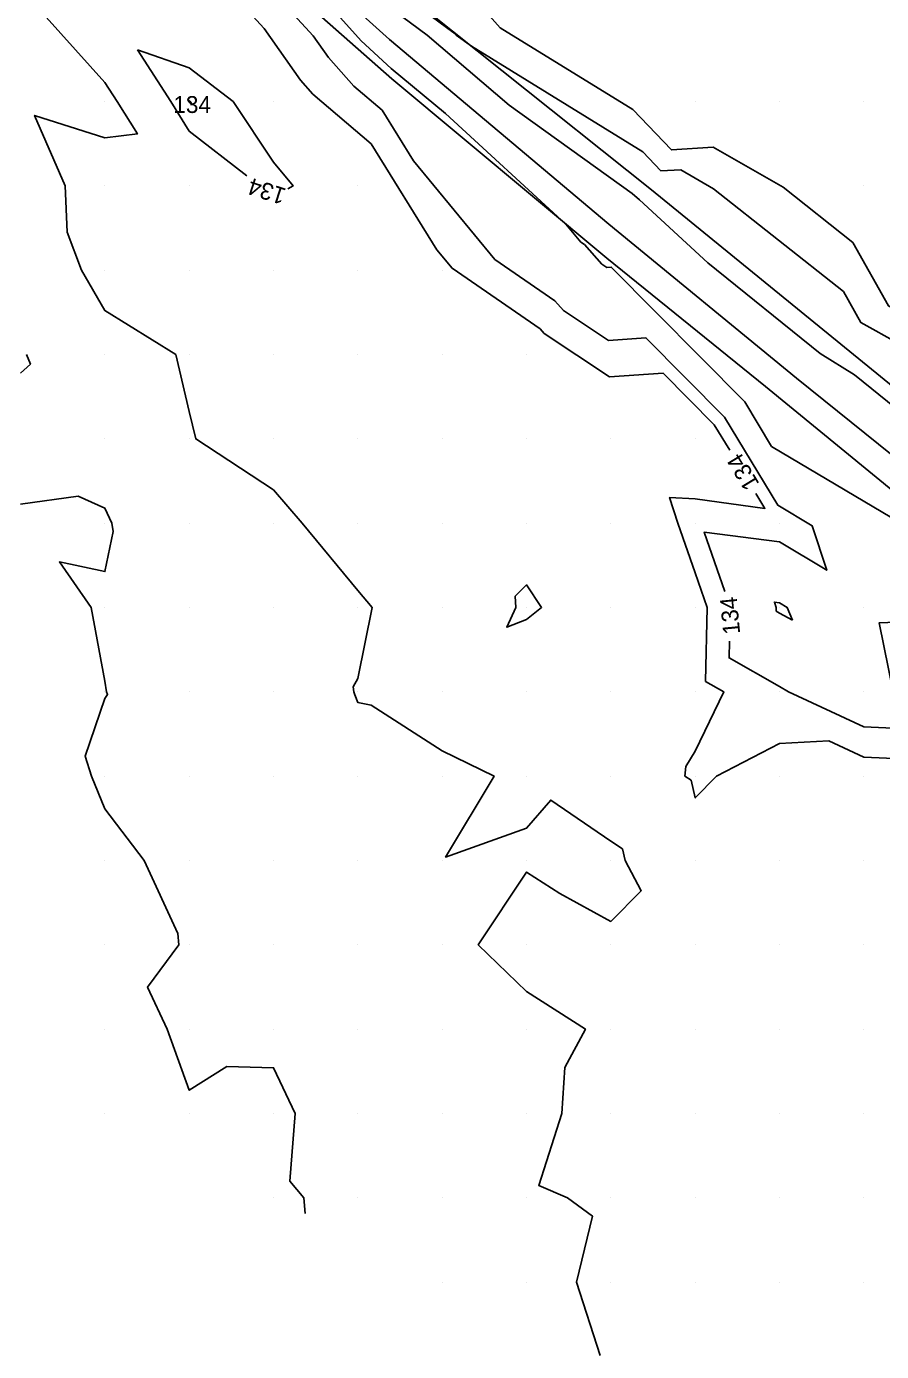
# Model space of a CAD drawing. Extents: x 2354170 to 2357230, y 866100 to 868290.
# Drawn here: x 2354990.7 to 2355092.1, y 867231.8 to 867388.9 of the extents above; entities that cross this region are included whole.
import ezdxf

# ---------------------------------------------------------------- set-up
doc = ezdxf.new("R2010")
doc.units = 0
for name, color, linetype in [('Default', 7, 'Continuous'), ('DTM Contours Minor', 7, 'Continuous'), ('DTM Contours Minor Text', 7, 'Continuous'), ('Exist DTM QL2 LIDAR Elevation Point', 7, 'Continuous'), ('PH Exist DTM Breakline', 7, 'Continuous')]:
    doc.layers.add(name, color=color, linetype=linetype)

msp = doc.modelspace()

# ---------------------------------------------------------------- linework, layer by layer
at = {"layer": 'Default'}
for points in [[(2355106.88, 867346.9), (2355102.18, 867350.64), (2355092.9, 867355.77), (2355088.66, 867363.29), (2355080.4, 867369.84), (2355072.11, 867374.59), (2355067.14, 867374.28), (2355062.56, 867379.07), (2355046.85, 867388.77), (2355044.03, 867391.9), (2355032.74, 867398.24), (2355030.89, 867399.72), (2355029.35, 867400.43), (2355028.09, 867400.68), (2355026.45, 867401.96)], [(2355002.92, 867397.36), (2355007.73, 867400.8), (2355018.86, 867388.68), (2355023.14, 867382.55), (2355024.61, 867380.9), (2355031.55, 867374.98), (2355039.34, 867362.43), (2355041.14, 867360.25), (2355051.56, 867353.04), (2355052.04, 867352.51), (2355059.8, 867347.37), (2355066.16, 867347.79), (2355072.22, 867341.68), (2355074.06, 867338.65)], [(2355198.39, 867249.97), (2355187.27, 867259.93), (2355180.42, 867265.38), (2355175.56, 867269.74), (2355167.49, 867277.11), (2355152.65, 867292.54), (2355145.83, 867297.52), (2355143.62, 867300.08), (2355127.24, 867315.15), (2355122.38, 867319.86), (2355121.91, 867320.21), (2355110.98, 867330.24), (2355105.72, 867333.97), (2355088.86, 867347.6), (2355084.78, 867350.15), (2355071.45, 867360.89), (2355063.34, 867368.37), (2355062.48, 867369.12), (2355047.91, 867379.58), (2355038.19, 867387.88), (2355031.33, 867392.97)], [(2354993.01, 867390.02), (2354999.97, 867382.26), (2355001.42, 867380.02), (2355003.81, 867376.18), (2354999.97, 867375.69), (2354991.63, 867378.36), (2354995.27, 867370.01), (2354995.47, 867364.52), (2354997.2, 867360.01), (2354999.97, 867355.22), (2355008.38, 867350.01), (2355009.97, 867343.27), (2355010.73, 867340.01), (2355019.97, 867333.95), (2355023.36, 867330.01), (2355029.97, 867322.03), (2355031.65, 867320.01), (2355029.97, 867311.6), (2355029.4, 867310.59), (2355029.48, 867310.01), (2355029.6, 867309.64), (2355029.97, 867308.73), (2355031.55, 867308.43), (2355039.97, 867303.01), (2355046.12, 867300.01), (2355040.36, 867290.41), (2355049.97, 867293.84), (2355052.83, 867297.16), (2355059.97, 867292.31), (2355061.34, 867291.38), (2355061.66, 867290.01), (2355063.56, 867286.42), (2355059.97, 867282.77), (2355053.92, 867286.07), (2355049.97, 867288.63), (2355044.23, 867280.01), (2355049.97, 867274.48), (2355056.95, 867270.01), (2355054.52, 867265.47), (2355054.14, 867260.01), (2355051.41, 867251.45), (2355054.82, 867250.01), (2355057.78, 867247.82), (2355055.9, 867240.01), (2355058.69, 867231.3)], [(2355027.2, 867390.72), (2355030.35, 867387.23), (2355033.92, 867383.94), (2355040.35, 867378.59), (2355054.64, 867365.47), (2355056.4, 867363.35), (2355056.82, 867363.06), (2355058.9, 867360.74), (2355059.5, 867360.34), (2355060, 867360.38), (2355075.85, 867344.38), (2355079.03, 867339.12), (2355096.48, 867328.73)], [(2355003.84, 867386.15), (2355009.97, 867384.03), (2355015.16, 867380.02), (2355019.97, 867372.82), (2355022.27, 867370.01), (2355021.65, 867369.66)], [(2355016.79, 867371.22), (2355009.97, 867376.52), (2355007.8, 867380.02), (2355003.84, 867386.15)], [(2354990.66, 867350.01), (2354991.13, 867348.86), (2354989.97, 867347.79)], [(2354989.97, 867332.28), (2354996.79, 867333.2), (2354999.97, 867331.77), (2355000.77, 867330.01), (2355000.94, 867329.04), (2354999.97, 867324.26), (2354994.57, 867325.42), (2354998.33, 867320.01), (2354999.97, 867311.26), (2355000.15, 867310.01), (2355000.29, 867309.7), (2354999.97, 867309.22), (2354997.62, 867302.36), (2354998.37, 867300.01), (2354999.97, 867296.14), (2355004.62, 867290.01), (2355008.63, 867281.36), (2355008.74, 867280.01), (2355005.03, 867274.96), (2355007.34, 867270.01), (2355009.97, 867262.75), (2355014.44, 867265.55), (2355019.97, 867265.43), (2355022.53, 867260.01), (2355021.91, 867251.95), (2355023.54, 867250.01), (2355023.71, 867248.15)], [(2355077.17, 867333.52), (2355078.23, 867331.75), (2355069.97, 867332.88), (2355066.93, 867333.06), (2355067.92, 867330.01), (2355069.97, 867324.13), (2355071.39, 867320.01), (2355071.2, 867311.24), (2355073.35, 867310.01), (2355069.97, 867302.95), (2355068.86, 867301.13), (2355068.75, 867300.01), (2355069.48, 867299.52), (2355069.97, 867297.42), (2355072.49, 867300.01), (2355079.97, 867303.89), (2355085.8, 867304.19), (2355089.97, 867302.24), (2355098.06, 867301.92), (2355096.44, 867310.01), (2355095.55, 867314.44), (2355099.59, 867314.59)], [(2355048.7, 867320.01), (2355048.63, 867321.35), (2355049.97, 867322.68), (2355051.75, 867320.01), (2355049.97, 867318.57), (2355047.62, 867317.66), (2355048.7, 867320.01)], [(2355081.49, 867318.49), (2355080.88, 867320.01), (2355079.97, 867320.56), (2355079.35, 867320.64), (2355079.56, 867320.01), (2355079.55, 867319.59), (2355079.97, 867319.35), (2355081.49, 867318.49)]]:
    msp.add_lwpolyline(points, dxfattribs=at)
at = {"layer": 'DTM Contours Minor'}
for points in [[(2355120.59, 867328.57), (2355113.74, 867335.73), (2355109.79, 867338.84), (2355094.16, 867351.28), (2355089.61, 867353.8), (2355087.53, 867357.48), (2355072.15, 867369.68), (2355068.25, 867371.92), (2355065.9, 867371.78), (2355063.74, 867374.03), (2355043.44, 867386.58), (2355041.62, 867387.89), (2355041.21, 867388.24), (2355029.74, 867396.76), (2355028.67, 867397.51), (2355025.68, 867399.94), (2355006.25, 867415.57), (2355005.43, 867416.13), (2354992, 867426.93), (2354983.12, 867432.35), (2354978.54, 867434.87), (2354962.63, 867448.83)], [(2355009.57, 867404.25), (2355024.68, 867387.81), (2355026.49, 867385.23), (2355029.5, 867381.83), (2355032.83, 867379), (2355036.56, 867372.99), (2355046.22, 867361.28), (2355053.31, 867356.38), (2355054.33, 867355.25), (2355059.7, 867351.69), (2355064.11, 867351.99), (2355073.43, 867342.58), (2355079.75, 867332.14), (2355083.83, 867329.71), (2355085.56, 867324.43), (2355079.97, 867327.81), (2355071.04, 867328.95), (2355073.46, 867321.92)], [(2355010.33, 867379.66), (2355010.09, 867380.02), (2355009.97, 867380.11), (2355009.83, 867380.15), (2355009.92, 867380.02), (2355009.97, 867379.94), (2355010.33, 867379.66)], [(2355093.45, 867310.01), (2355091.79, 867318.2), (2355099.96, 867318.51)], [(2355074.03, 867316.03), (2355073.98, 867314.02), (2355079.97, 867310.62), (2355081.03, 867310.01), (2355089.97, 867305.84), (2355094.32, 867305.67)]]:
    msp.add_lwpolyline(points, dxfattribs=at)
at = {"layer": 'Exist DTM QL2 LIDAR Elevation Point'}
for p, q in [((2354999.97, 867380.02), (2354999.97, 867380.02)), ((2355009.97, 867380.02), (2355009.97, 867380.02)), ((2355019.97, 867380.02), (2355019.97, 867380.02)), ((2355069.97, 867380.02), (2355069.97, 867380.02)), ((2355079.97, 867380.02), (2355079.97, 867380.02)), ((2355089.97, 867380.02), (2355089.97, 867380.02)), ((2354999.97, 867370.01), (2354999.97, 867370.01)), ((2355009.97, 867370.01), (2355009.97, 867370.01)), ((2355019.97, 867370.01), (2355019.97, 867370.01)), ((2355029.97, 867370.01), (2355029.97, 867370.01)), ((2355089.97, 867370.01), (2355089.97, 867370.01)), ((2354999.97, 867360.01), (2354999.97, 867360.01)), ((2355009.97, 867360.01), (2355009.97, 867360.01)), ((2355019.97, 867360.01), (2355019.97, 867360.01)), ((2355029.97, 867360.01), (2355029.97, 867360.01)), ((2355039.97, 867360.01), (2355039.97, 867360.01)), ((2354999.97, 867350.01), (2354999.97, 867350.01)), ((2355009.97, 867350.01), (2355009.97, 867350.01)), ((2355019.97, 867350.01), (2355019.97, 867350.01)), ((2355029.97, 867350.01), (2355029.97, 867350.01)), ((2355039.97, 867350.01), (2355039.97, 867350.01)), ((2355049.97, 867350.01), (2355049.97, 867350.01)), ((2354999.97, 867340.01), (2354999.97, 867340.01)), ((2355009.97, 867340.01), (2355009.97, 867340.01)), ((2355019.97, 867340.01), (2355019.97, 867340.01)), ((2355029.97, 867340.01), (2355029.97, 867340.01)), ((2355039.97, 867340.01), (2355039.97, 867340.01)), ((2355049.97, 867340.01), (2355049.97, 867340.01)), ((2355059.97, 867340.01), (2355059.97, 867340.01)), ((2355069.97, 867340.01), (2355069.97, 867340.01)), ((2354999.97, 867330.01), (2354999.97, 867330.01)), ((2355009.97, 867330.01), (2355009.97, 867330.01)), ((2355019.97, 867330.01), (2355019.97, 867330.01)), ((2355029.97, 867330.01), (2355029.97, 867330.01)), ((2355039.97, 867330.01), (2355039.97, 867330.01)), ((2355049.97, 867330.01), (2355049.97, 867330.01)), ((2355059.97, 867330.01), (2355059.97, 867330.01)), ((2355069.97, 867330.01), (2355069.97, 867330.01)), ((2355079.97, 867330.01), (2355079.97, 867330.01)), ((2354999.97, 867320.01), (2354999.97, 867320.01)), ((2355009.97, 867320.01), (2355009.97, 867320.01)), ((2355019.97, 867320.01), (2355019.97, 867320.01)), ((2355029.97, 867320.01), (2355029.97, 867320.01)), ((2355039.97, 867320.01), (2355039.97, 867320.01)), ((2355049.97, 867320.01), (2355049.97, 867320.01)), ((2355059.97, 867320.01), (2355059.97, 867320.01)), ((2355069.97, 867320.01), (2355069.97, 867320.01)), ((2355079.97, 867320.01), (2355079.97, 867320.01)), ((2355089.97, 867320.01), (2355089.97, 867320.01)), ((2354999.97, 867310.01), (2354999.97, 867310.01)), ((2355009.97, 867310.01), (2355009.97, 867310.01)), ((2355019.97, 867310.01), (2355019.97, 867310.01)), ((2355029.97, 867310.01), (2355029.97, 867310.01)), ((2355039.97, 867310.01), (2355039.97, 867310.01)), ((2355049.97, 867310.01), (2355049.97, 867310.01)), ((2355059.97, 867310.01), (2355059.97, 867310.01)), ((2355069.97, 867310.01), (2355069.97, 867310.01)), ((2355079.97, 867310.01), (2355079.97, 867310.01)), ((2355089.97, 867310.01), (2355089.97, 867310.01)), ((2354999.97, 867300.01), (2354999.97, 867300.01)), ((2355009.97, 867300.01), (2355009.97, 867300.01)), ((2355019.97, 867300.01), (2355019.97, 867300.01)), ((2355029.97, 867300.01), (2355029.97, 867300.01)), ((2355039.97, 867300.01), (2355039.97, 867300.01)), ((2355049.97, 867300.01), (2355049.97, 867300.01)), ((2355059.97, 867300.01), (2355059.97, 867300.01)), ((2355069.97, 867300.01), (2355069.97, 867300.01)), ((2355079.97, 867300.01), (2355079.97, 867300.01)), ((2355089.97, 867300.01), (2355089.97, 867300.01)), ((2354999.97, 867290.01), (2354999.97, 867290.01)), ((2355009.97, 867290.01), (2355009.97, 867290.01)), ((2355019.97, 867290.01), (2355019.97, 867290.01)), ((2355029.97, 867290.01), (2355029.97, 867290.01)), ((2355039.97, 867290.01), (2355039.97, 867290.01)), ((2355049.97, 867290.01), (2355049.97, 867290.01)), ((2355059.97, 867290.01), (2355059.97, 867290.01)), ((2355069.97, 867290.01), (2355069.97, 867290.01)), ((2355079.97, 867290.01), (2355079.97, 867290.01)), ((2355089.97, 867290.01), (2355089.97, 867290.01)), ((2354999.97, 867280.01), (2354999.97, 867280.01)), ((2355009.97, 867280.01), (2355009.97, 867280.01)), ((2355019.97, 867280.01), (2355019.97, 867280.01)), ((2355029.97, 867280.01), (2355029.97, 867280.01)), ((2355039.97, 867280.01), (2355039.97, 867280.01)), ((2355049.97, 867280.01), (2355049.97, 867280.01)), ((2355059.97, 867280.01), (2355059.97, 867280.01)), ((2355069.97, 867280.01), (2355069.97, 867280.01)), ((2355079.97, 867280.01), (2355079.97, 867280.01)), ((2355089.97, 867280.01), (2355089.97, 867280.01)), ((2354999.97, 867270.01), (2354999.97, 867270.01)), ((2355009.97, 867270.01), (2355009.97, 867270.01)), ((2355019.97, 867270.01), (2355019.97, 867270.01)), ((2355029.97, 867270.01), (2355029.97, 867270.01)), ((2355039.97, 867270.01), (2355039.97, 867270.01)), ((2355049.97, 867270.01), (2355049.97, 867270.01)), ((2355059.97, 867270.01), (2355059.97, 867270.01)), ((2355069.97, 867270.01), (2355069.97, 867270.01)), ((2355079.97, 867270.01), (2355079.97, 867270.01)), ((2355089.97, 867270.01), (2355089.97, 867270.01)), ((2354999.97, 867260.01), (2354999.97, 867260.01)), ((2355009.97, 867260.01), (2355009.97, 867260.01)), ((2355019.97, 867260.01), (2355019.97, 867260.01)), ((2355029.97, 867260.01), (2355029.97, 867260.01)), ((2355039.97, 867260.01), (2355039.97, 867260.01)), ((2355049.97, 867260.01), (2355049.97, 867260.01)), ((2355059.97, 867260.01), (2355059.97, 867260.01)), ((2355069.97, 867260.01), (2355069.97, 867260.01)), ((2355079.97, 867260.01), (2355079.97, 867260.01)), ((2355089.97, 867260.01), (2355089.97, 867260.01)), ((2355019.97, 867250.01), (2355019.97, 867250.01)), ((2355029.97, 867250.01), (2355029.97, 867250.01)), ((2355039.97, 867250.01), (2355039.97, 867250.01)), ((2355049.97, 867250.01), (2355049.97, 867250.01)), ((2355059.97, 867250.01), (2355059.97, 867250.01)), ((2355069.97, 867250.01), (2355069.97, 867250.01)), ((2355079.97, 867250.01), (2355079.97, 867250.01)), ((2355089.97, 867250.01), (2355089.97, 867250.01)), ((2355039.97, 867240.01), (2355039.97, 867240.01)), ((2355049.97, 867240.01), (2355049.97, 867240.01)), ((2355059.97, 867240.01), (2355059.97, 867240.01)), ((2355069.97, 867240.01), (2355069.97, 867240.01)), ((2355079.97, 867240.01), (2355079.97, 867240.01)), ((2355089.97, 867240.01), (2355089.97, 867240.01))]:
    msp.add_line(p, q, dxfattribs=at)
at = {"layer": 'PH Exist DTM Breakline'}
for points in [[(2354959.91, 867451.23), (2354980.37, 867432.91), (2355007.19, 867410.5), (2355025.02, 867395.22), (2355033.7, 867387.36), (2355059.73, 867365.46), (2355081.96, 867347.19), (2355094.94, 867336.78), (2355119.41, 867315.01), (2355139.32, 867297.49), (2355161.56, 867277.52), (2355180.56, 867261.15), (2355194.29, 867250.82), (2355213.16, 867234.84), (2355219.91, 867231.06), (2355229.72, 867220.77)], [(2355202.75, 867249.08), (2355171.42, 867276.84), (2355145.7, 867301.34), (2355109.69, 867332.94), (2355064.8, 867369.55), (2355029.27, 867397.88), (2354988.22, 867431.32), (2354962.55, 867451.45)], [(2354960.11, 867447.89), (2354976.9, 867433.29), (2355006.43, 867407.03), (2355034, 867382.69), (2355059.48, 867361.44), (2355078.3, 867346.21), (2355099.95, 867328.46), (2355110.49, 867318), (2355125.85, 867305.31), (2355149.72, 867282.99), (2355163.32, 867271.23), (2355187.97, 867250.1), (2355204.74, 867236.68)]]:
    msp.add_lwpolyline(points, dxfattribs=at)

# ---------------------------------------------------------------- texts
at = {"layer": 'Default'}
for rotation, p in [(162.1519, (2355021.59, 867369.63)), (121.2163, (2355077.63, 867334.68))]:
    msp.add_text('134', height=2, rotation=rotation, dxfattribs=at).set_placement(p)
at = {"layer": 'DTM Contours Minor Text'}
msp.add_text('134', height=2, dxfattribs=at).set_placement((2355008.08, 867378.66))
msp.add_text('134', height=2, rotation=95.5354, dxfattribs=at).set_placement((2355075.3, 867316.9))

doc.saveas('drawing.dxf')
